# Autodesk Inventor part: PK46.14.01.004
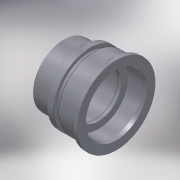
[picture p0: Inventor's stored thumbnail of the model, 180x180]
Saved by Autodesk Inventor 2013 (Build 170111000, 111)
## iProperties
Shininess: 64.0
Length Units: 11269
Angle Units: 11279
Time Units: 11290
Mass Units: 11283
Length Display Precision: 3
Angle Display Precision: 2
Compacted: True
Part Number: PK46.14.01.004
Document SubType Name: Modeling
Created: 2004-11
Material: Сталь высокопрочная низколегированная
Designer: ELarisa
Manufacturer: Standard
Standards Organization: Custom
Density: 7.84 g/cm^3
Density: 0.0
Volumn: 0.0
Area: 0.0
PropertySet Name: Model Information
Control State: 0
Master: False
Checked Out: False
Checked Out Date: 2008-10-15
Last Check In Date: 2008-10-15
Author: ELarisa
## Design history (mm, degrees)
sketch "Эскиз1"
  geometry: L1 (-20, -21.335)-(-20, 21.665); L2 (-20, 21.665)-(6, 21.665); L3 (6, 21.665)-(6, 28.665); L4 (6, 28.665)-(16, 28.665); L5 (16, 28.665)-(16, 24.065); L6 (16, 24.065)-(23, 24.065); L7 (23, 24.065)-(23, 28.665); L8 (23, 28.665)-(47, 28.665); L9 (47, 28.665)-(47, 33.665); L10 (47, 33.665)-(54, 33.665); L11 (54, 33.665)-(54, -21.335); L12 (54, -21.335)-(-20, -21.335); L13 (-16, 10.665)-(-16, 12.665); L14 (-16, 12.665)-(24, 12.665); L15 (24, 12.665)-(24, 10.665); L16 (29, 10.665)-(29, 20.165); L17 (29, 20.165)-(49, 20.165); L18 (49, 20.165)-(54, 21.505); L19 (24, 10.665)-(29, 10.665); L20 (-20, 10.665)-(-16, 10.665)
  constraints: 40 end point, 11 parallel, 7 perpendicular, 2 collinear, 2 point on line, 1 vertical
  dimensions: "d0" = 43 distance of L1.start L1.end; "d1" = 55 distance of L10.end L11.end; "d2" = 40 distance of L13.end L14.end; "d3" = 74 distance of L11.end L1.start; "d5" = 25 distance from line of L11 L16.end; "d6" = 5 horizontal distance of L17.end L18.end; "d7" = 67 distance between parallel lines of L1 L9; "d8" = 43 distance from line of L7.end L1; "d9" = 7 distance of L5.end L6.end; "d10" = 26 distance between parallel lines of L3 L1; "d11" = 50 distance between parallel lines of L12 L4; "d12" = 45.4 distance between parallel lines of L12 L6; "d13" = 41.5 distance between parallel lines of L12 L17; "d14" = 15 deg angle of L18 L17; "d15" = 34 distance between parallel lines of L12 L14; "d16" = 32 distance between parallel lines of L12 L19; "d17" = 4 distance of L20.start L13.start
revolve "Вращение1" sketch "Эскиз1" stored, may be unused: angle "d18" = 90 deg
chamfer "Фаска1" distance "d19" = 1; stored, may be unused: second distance "d20" = 2, angle "d23" = 45 deg
fillet "Сопряжение1" dims "d21" = 0.2
fillet "Сопряжение2" dims "d22" = 0.6
body "Solid1"
